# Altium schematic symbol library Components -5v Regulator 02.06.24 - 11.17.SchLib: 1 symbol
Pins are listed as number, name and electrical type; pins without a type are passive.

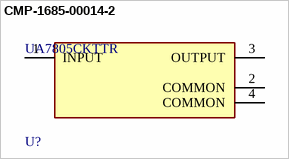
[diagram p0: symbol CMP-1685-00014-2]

## CMP-1685-00014-2
designator U?, comment UA7805CKTTR
IC REG LIN 5V 1.5A DDPAK/TO263-3; Output Type: Fixed; Quiescent Current: 8mA; Dropout Voltage: 2V; Max Input Voltage: 25V; Number of Regulators: 1; Max Output Voltage: 5.2V; Polarity: Positive; Min Output Voltage: 4.8V; Power Supply Rejection Ratio (PSRR): 78dB; Min Input Voltage: 7V; Power Rating: 15W
footprint FP-KTT0003A-MFG
pins: 1 INPUT (power), 2 COMMON (power), 3 OUTPUT (power), 4 COMMON (power)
